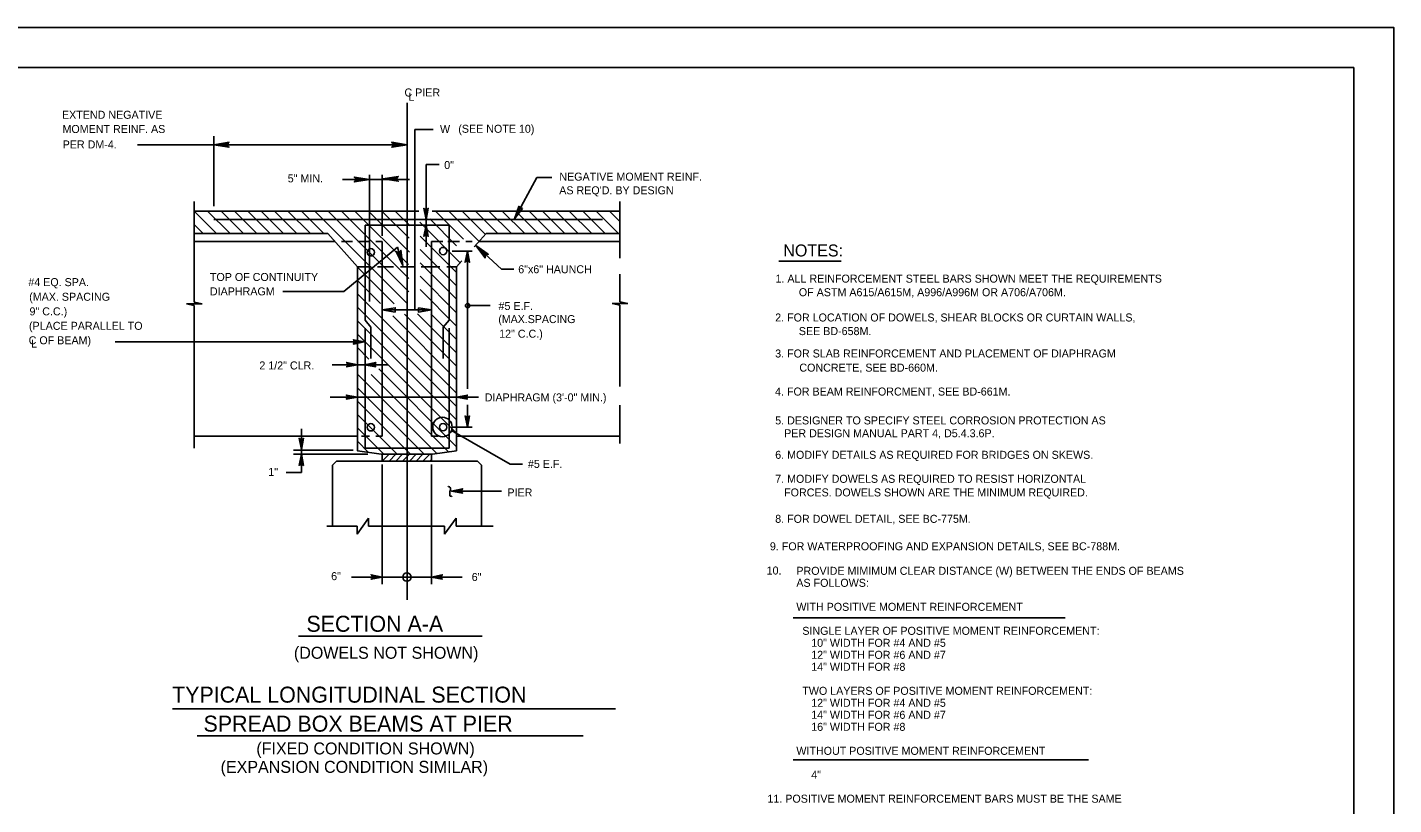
# Model space of a CAD drawing. Extents: x 641517 to 642372, y 298537 to 300319.
# Drawn here: x 641846 to 642358, y 300027 to 300319 of the extents above; entities that cross this region are included whole.
import ezdxf

# ---------------------------------------------------------------- set-up
doc = ezdxf.new("R2010")
doc.units = 0
for name, color, linetype in [('1', 7, 'Continuous'), ('2', 7, 'Continuous'), ('PLT-BNDY', 7, 'Continuous')]:
    doc.layers.add(name, color=color, linetype=linetype)

msp = doc.modelspace()

# ---------------------------------------------------------------- linework, layer by layer
at = {"layer": '2'}
for p, q in [((641557.05, 300303.62), (642343.05, 300303.62)), ((642343.05, 300303.62), (642343.05, 299739.62)), ((641988.08, 300290.27), (641988.08, 300103.92)), ((641915.63, 300251.52), (641915.63, 300277.77)), ((641991.07, 300212.72), (641991.07, 300280.32)), ((641997.88, 300280.32), (641991.07, 300280.32)), ((641988.08, 300274.62), (641886.98, 300274.62)), ((642000.17, 300267.18), (641995.32, 300267.18)), ((641995.32, 300246.57), (641995.32, 300267.18)), ((641989.03, 300261.57), (641963.93, 300261.57)), ((641973.98, 300215.82), (641973.98, 300263.32)), ((641978.78, 300240.42), (641978.78, 300263.32)), ((642028.37, 300246.79), (642036.78, 300262.28)), ((642042.39, 300262.28), (642036.78, 300262.28)), ((641908.28, 300215.52), (641908.28, 300253.32)), ((642067.88, 300253.32), (642067.88, 300232.08)), ((641908.28, 300249.35), (641908.66, 300249.72)), ((641908.28, 300249.72), (641908.28, 300249.72)), ((641908.28, 300249.72), (641916.68, 300241.32)), ((641908.28, 300249.72), (641992.56, 300249.72)), ((641913.31, 300249.72), (641921.71, 300241.32)), ((642061.4, 300246.57), (641915.63, 300246.57)), ((641918.33, 300249.72), (641926.73, 300241.32)), ((641923.35, 300249.72), (641931.75, 300241.32)), ((641928.38, 300249.72), (641936.78, 300241.32)), ((641933.4, 300249.72), (641941.8, 300241.32)), ((641938.42, 300249.72), (641946.82, 300241.32)), ((641943.45, 300249.72), (641951.85, 300241.32)), ((641948.47, 300249.72), (641956.87, 300241.32)), ((641953.49, 300249.72), (641988.23, 300214.99)), ((641958.52, 300249.72), (641988.82, 300219.42)), ((641963.54, 300249.72), (641988.8, 300224.47)), ((641968.56, 300249.72), (641988.66, 300229.63)), ((641973.59, 300249.72), (641989.02, 300234.29)), ((641978.61, 300249.72), (641988.83, 300239.51)), ((641983.63, 300249.72), (641989.2, 300244.16)), ((641995.32, 300244.46), (641995.32, 300246.57)), ((641996.58, 300246.83), (642006.67, 300236.73)), ((641997.47, 300249.72), (642067.88, 300249.72)), ((641998.7, 300249.72), (642009.28, 300239.14)), ((642003.73, 300249.72), (642015.12, 300238.33)), ((642008.75, 300249.72), (642017.49, 300240.99)), ((642013.77, 300249.72), (642022.17, 300241.32)), ((642018.8, 300249.72), (642027.2, 300241.32)), ((642023.82, 300249.72), (642032.22, 300241.32)), ((642028.84, 300249.72), (642037.24, 300241.32)), ((642033.87, 300249.72), (642042.27, 300241.32)), ((642038.89, 300249.72), (642047.29, 300241.32)), ((642043.91, 300249.72), (642052.31, 300241.32)), ((642048.94, 300249.72), (642057.34, 300241.32)), ((642053.96, 300249.72), (642062.36, 300241.32)), ((642058.98, 300249.72), (642067.38, 300241.32)), ((642064.01, 300249.72), (642067.88, 300245.85)), ((641908.28, 300244.7), (641911.66, 300241.32)), ((641908.28, 300241.32), (641958.38, 300241.32)), ((641969.48, 300228.87), (641958.38, 300241.32)), ((641972.33, 300244.43), (642003.83, 300244.43)), ((641972.33, 300244.43), (641972.33, 300208.77)), ((641992.83, 300245.55), (642008.02, 300230.37)), ((641995.32, 300236.25), (641995.32, 300244.43)), ((642003.83, 300244.43), (642003.83, 300208.77)), ((642017.78, 300241.32), (642013.3, 300236.29)), ((642017.78, 300241.32), (642067.88, 300241.32)), ((641961.08, 300238.32), (641908.28, 300238.32)), ((641967.69, 300238.32), (641963.48, 300238.32)), ((641984.46, 300236.21), (641964.38, 300219.53)), ((641969.66, 300238.32), (641974.05, 300238.32)), ((641976.38, 300238.32), (641978.78, 300238.32)), ((641978.78, 300165.27), (641978.78, 300238.32)), ((641986.54, 300229.34), (641984.46, 300236.21)), ((641993, 300240.36), (642006.68, 300226.67)), ((641997.23, 300165.27), (641997.23, 300238.32)), ((642001.45, 300238.32), (641997.23, 300238.32)), ((642003.42, 300238.32), (642007.81, 300238.32)), ((642010.14, 300238.32), (642012.54, 300238.32)), ((642013.88, 300236.82), (642023.48, 300227.97)), ((642015.08, 300238.32), (642067.88, 300238.32)), ((641993, 300235.34), (642006.68, 300221.65)), ((642012.49, 300234.7), (642005.03, 300234.7)), ((642008.62, 300231.04), (642006.68, 300228.87)), ((642010.77, 300183.08), (642010.77, 300234.7)), ((642127.54, 300230.95), (642150.82, 300230.95)), ((641969.48, 300159.87), (641969.48, 300228.87)), ((641969.48, 300228.87), (641974.58, 300228.87)), ((641969.48, 300228.71), (641983.29, 300214.9)), ((641976.98, 300228.87), (641982.98, 300228.87)), ((641985.68, 300228.87), (641990.63, 300228.87)), ((641993, 300230.31), (642006.68, 300216.63)), ((641993, 300225.29), (642006.68, 300211.6)), ((641993.33, 300228.87), (642000.35, 300228.87)), ((642003.05, 300228.87), (642006.68, 300228.87)), ((642006.68, 300228.87), (642006.68, 300159.87)), ((642028.13, 300227.97), (642023.48, 300227.97)), ((642067.88, 300215.67), (642067.88, 300226.02)), ((641969.48, 300223.69), (641978.08, 300215.1)), ((641993, 300220.27), (642006.68, 300206.58)), ((641908.28, 300215.52), (641911.28, 300214.92)), ((641964.38, 300219.53), (641941.47, 300219.53)), ((641969.48, 300218.66), (642006.68, 300181.46)), ((642065.03, 300215.07), (642070.88, 300215.07)), ((642065.03, 300215.07), (642067.88, 300214.47)), ((642067.88, 300215.67), (642070.88, 300215.07)), ((641905.43, 300214.92), (641911.28, 300214.92)), ((641905.43, 300214.92), (641908.28, 300214.32)), ((641908.28, 300160.77), (641908.28, 300214.32)), ((641969.48, 300213.64), (642006.68, 300176.44)), ((641997.23, 300212.65), (641978.78, 300212.65)), ((641982.7, 300210.47), (642006.68, 300186.49)), ((641987.13, 300211.07), (642006.68, 300191.51)), ((641992.06, 300211.15), (642006.68, 300196.53)), ((641997, 300211.24), (642006.68, 300201.56)), ((642010.77, 300214.29), (642019.25, 300214.29)), ((642067.88, 300184), (642067.88, 300214.47)), ((641969.48, 300208.62), (642006.68, 300171.42)), ((641974.54, 300206.2), (641972.33, 300208.77)), ((641972.33, 300205.77), (641972.33, 300160.77)), ((641974.54, 300206.2), (641974.54, 300194.43)), ((642001.64, 300206.21), (642003.83, 300208.77)), ((642001.64, 300206.21), (642001.64, 300194.43)), ((642003.83, 300205.77), (642003.83, 300160.77)), ((641972.03, 300200.73), (641878.68, 300200.73)), ((641969.48, 300203.59), (642006.68, 300166.39)), ((641969.48, 300198.57), (641973.81, 300194.24)), ((641981.03, 300192.07), (641960.03, 300192.07)), ((641977.49, 300190.56), (642006.68, 300161.37)), ((641969.48, 300188.52), (641999.25, 300158.76)), ((641974.61, 300188.42), (642003.62, 300159.41)), ((641969.48, 300179.97), (641959.28, 300179.97)), ((641969.48, 300183.5), (641994.46, 300158.52)), ((642006.68, 300179.97), (641969.48, 300179.97)), ((642014.93, 300179.97), (642006.68, 300179.97)), ((641969.48, 300178.48), (641989.44, 300158.52)), ((642010.77, 300168.68), (642010.77, 300177.05)), ((642067.88, 300162.57), (642067.88, 300176.97)), ((641969.48, 300173.45), (641984.41, 300158.52)), ((641908.28, 300165.27), (641969.63, 300165.27)), ((641948.48, 300158.52), (641948.48, 300168.12)), ((641969.48, 300168.43), (641979.39, 300158.52)), ((641970.99, 300165.27), (641974.05, 300165.27)), ((641976.38, 300165.27), (641978.78, 300165.27)), ((641997.23, 300165.27), (641999.8, 300165.27)), ((642004.75, 300167.43), (642026.74, 300154.82)), ((642012.49, 300168.68), (642005.03, 300168.68)), ((642006.53, 300165.27), (642067.88, 300165.27)), ((641967.83, 300160.02), (641945.48, 300160.02)), ((641969.48, 300163.41), (641973.65, 300159.24)), ((641969.48, 300160.03), (641969.67, 300159.84)), ((641969.48, 300159.87), (641978.33, 300158.52)), ((641972.33, 300160.77), (642003.83, 300160.77)), ((641997.68, 300158.52), (642006.68, 300159.87)), ((641973.38, 300158.52), (641945.48, 300158.52)), ((641948.48, 300151.63), (641948.48, 300158.52)), ((641960.18, 300154.47), (641961.68, 300155.97)), ((641960.18, 300154.47), (641960.18, 300131.52)), ((641961.68, 300155.97), (642014.48, 300155.97)), ((641997.68, 300158.52), (641978.33, 300158.52)), ((641978.78, 300155.97), (641978.78, 300158.52)), ((641978.78, 300158.52), (641978.78, 300158.52)), ((641978.78, 300158.52), (641978.78, 300158.52)), ((641978.78, 300158.52), (641978.78, 300158.52)), ((641978.78, 300155.98), (641981.33, 300158.52)), ((641978.78, 300154.73), (641978.78, 300109.77)), ((641981.33, 300155.97), (641983.88, 300158.52)), ((641983.87, 300155.97), (641986.42, 300158.52)), ((641986.42, 300155.97), (641988.97, 300158.52)), ((641988.96, 300155.97), (641991.51, 300158.52)), ((641991.51, 300155.97), (641994.06, 300158.52)), ((641994.05, 300155.97), (641996.6, 300158.52)), ((641996.6, 300155.97), (641997.23, 300156.61)), ((641997.23, 300155.97), (641997.23, 300158.52)), ((641997.23, 300154.73), (641997.23, 300109.77)), ((642015.98, 300154.47), (642014.48, 300155.97)), ((642015.98, 300154.47), (642015.98, 300131.52)), ((642031.39, 300154.82), (642026.74, 300154.82)), ((641942.77, 300151.63), (641948.48, 300151.63)), ((642023.48, 300144.72), (642004.73, 300144.72)), ((641969.33, 300128.52), (641973.68, 300134.52)), ((641973.68, 300134.52), (641973.68, 300131.52)), ((642002.18, 300128.52), (642006.53, 300134.52)), ((642006.53, 300134.52), (642006.53, 300131.52)), ((641969.33, 300131.52), (641957.99, 300131.52)), ((641969.33, 300131.52), (641969.33, 300128.52)), ((642002.18, 300131.52), (641973.68, 300131.52)), ((642002.18, 300131.52), (642002.18, 300128.52)), ((642020.33, 300131.52), (642006.53, 300131.52)), ((641988.08, 300120.42), (641988.08, 300120.42)), ((642008.78, 300112.47), (641967.23, 300112.47)), ((642132.93, 300097.2), (642234.86, 300097.2)), ((641947.39, 300090.34), (642016.24, 300090.34)), ((641900.12, 300063.01), (642066.25, 300063.01)), ((641909.41, 300052.89), (642054.09, 300052.89)), ((642132.93, 300043.92), (642243.59, 300043.92))]:
    msp.add_line(p, q, dxfattribs=at)
for points in [[(641921.03, 300273.87), (641920.88, 300274.32), (641915.63, 300274.62), (641921.03, 300273.87), (641921.33, 300273.72), (641915.63, 300274.62), (641920.88, 300274.77), (641921.03, 300275.22), (641915.63, 300274.62), (641921.33, 300275.52), (641921.03, 300275.22)], [(641982.68, 300275.22), (641982.83, 300274.92), (641988.08, 300274.62), (641982.68, 300275.22), (641982.38, 300275.52), (641988.08, 300274.62), (641982.83, 300274.32), (641982.68, 300273.87), (641988.08, 300274.62), (641982.38, 300273.72), (641982.68, 300273.87)], [(641968.58, 300262.32), (641968.73, 300261.87), (641973.98, 300261.57), (641968.58, 300262.32), (641968.28, 300262.47), (641973.98, 300261.57), (641968.73, 300261.27), (641968.58, 300260.97), (641973.98, 300261.57), (641968.28, 300260.67), (641968.58, 300260.97)], [(641984.49, 300261.22), (641984.34, 300261.52), (641979.09, 300261.82), (641984.49, 300261.22), (641984.79, 300260.92), (641979.09, 300261.82), (641984.34, 300262.12), (641984.49, 300262.42), (641979.09, 300261.82), (641984.79, 300262.72), (641984.49, 300262.42)], [(641995.92, 300250.47), (641995.47, 300250.47), (641995.32, 300246.57), (641995.92, 300250.47), (641996.07, 300250.77), (641995.32, 300246.57), (641995.02, 300250.47), (641994.72, 300250.47), (641995.32, 300246.57), (641994.42, 300250.77), (641994.72, 300250.47)], [(641994.72, 300240.53), (641995.02, 300240.68), (641995.32, 300244.43), (641994.72, 300240.53), (641994.42, 300240.23), (641995.32, 300244.43), (641995.47, 300240.68), (641995.92, 300240.53), (641995.32, 300244.43), (641996.07, 300240.23), (641995.92, 300240.53)], [(642017.33, 300232.62), (642017.48, 300232.92), (642013.88, 300236.82), (642017.33, 300232.62), (642017.33, 300232.17), (642013.88, 300236.82), (642017.78, 300233.37), (642018.23, 300233.52), (642013.88, 300236.82), (642018.53, 300233.52), (642018.23, 300233.52)], [(641985.74, 300234.73), (641985.35, 300234.46), (641986.54, 300229.34), (641985.74, 300234.73), (641985.8, 300235.06), (641986.54, 300229.34), (641984.77, 300234.29), (641984.44, 300234.35), (641986.54, 300229.34), (641984.07, 300234.56), (641984.44, 300234.35)], [(642010.17, 300230.8), (642010.47, 300230.95), (642010.77, 300234.7), (642010.17, 300230.8), (642009.87, 300230.5), (642010.77, 300234.7), (642010.92, 300230.95), (642011.37, 300230.8), (642010.77, 300234.7), (642011.52, 300230.5), (642011.37, 300230.8)], [(641968.13, 300201.33), (641968.28, 300200.88), (641972.03, 300200.73), (641968.13, 300201.33), (641967.98, 300201.48), (641972.03, 300200.73), (641968.28, 300200.43), (641968.13, 300200.13), (641972.03, 300200.73), (641967.98, 300199.83), (641968.13, 300200.13)], [(641965.58, 300192.67), (641965.73, 300192.37), (641969.48, 300192.07), (641965.58, 300192.67), (641965.43, 300192.97), (641969.48, 300192.07), (641965.73, 300191.92), (641965.58, 300191.47), (641969.48, 300192.07), (641965.43, 300191.32), (641965.58, 300191.47)], [(641976.23, 300191.47), (641976.08, 300191.92), (641972.18, 300192.07), (641976.23, 300191.47), (641976.38, 300191.32), (641972.18, 300192.07), (641976.08, 300192.37), (641976.23, 300192.67), (641972.18, 300192.07), (641976.38, 300192.97), (641976.23, 300192.67)], [(641965.43, 300180.57), (641965.58, 300180.27), (641969.48, 300179.97), (641965.43, 300180.57), (641965.28, 300180.72), (641969.48, 300179.97), (641965.58, 300179.67), (641965.43, 300179.37), (641969.48, 300179.97), (641965.28, 300179.22), (641965.43, 300179.37)], [(642010.58, 300179.37), (642010.43, 300179.67), (642006.68, 300179.97), (642010.58, 300179.37), (642010.73, 300179.22), (642006.68, 300179.97), (642010.43, 300180.12), (642010.58, 300180.57), (642006.68, 300179.97), (642010.73, 300180.72), (642010.58, 300180.57)], [(642011.37, 300172.58), (642010.92, 300172.58), (642010.77, 300168.68), (642011.37, 300172.58), (642011.52, 300172.88), (642010.77, 300168.68), (642010.47, 300172.58), (642010.17, 300172.58), (642010.77, 300168.68), (642009.87, 300172.88), (642010.17, 300172.58)], [(641949.08, 300164.37), (641948.63, 300164.22), (641948.48, 300160.32), (641949.08, 300164.37), (641949.23, 300164.52), (641948.48, 300160.32), (641948.18, 300164.22), (641947.88, 300164.37), (641948.48, 300160.32), (641947.58, 300164.52), (641947.88, 300164.37)], [(641947.88, 300154.62), (641948.18, 300154.62), (641948.48, 300158.52), (641947.88, 300154.62), (641947.58, 300154.32), (641948.48, 300158.52), (641948.63, 300154.77), (641948.93, 300154.62), (641948.48, 300158.52), (641949.23, 300154.32), (641948.93, 300154.62)], [(642008.78, 300144.12), (642008.63, 300144.57), (642004.73, 300144.72), (642008.78, 300144.12), (642008.93, 300143.97), (642004.73, 300144.72), (642008.63, 300145.02), (642008.78, 300145.32), (642004.73, 300144.72), (642008.93, 300145.62), (642008.78, 300145.32)], [(641974.88, 300113.07), (641975.03, 300112.77), (641978.78, 300112.47), (641974.88, 300113.07), (641974.58, 300113.37), (641978.78, 300112.47), (641975.03, 300112.32), (641974.88, 300111.87), (641978.78, 300112.47), (641974.58, 300111.72), (641974.88, 300111.87)], [(642001.13, 300111.87), (642000.98, 300112.32), (641997.23, 300112.47), (642001.13, 300111.87), (642001.28, 300111.72), (641997.23, 300112.47), (642000.98, 300112.77), (642001.13, 300113.07), (641997.23, 300112.47), (642001.28, 300113.37), (642001.13, 300113.07)]]:
    msp.add_lwpolyline(points, dxfattribs=at)
for points in [[(642031.41, 300250.67), (642028.37, 300246.79), (642029.99, 300251.44)], [(641983.64, 300211.84), (641978.78, 300212.65), (641983.64, 300213.45)], [(641992.37, 300213.47), (641997.23, 300212.65), (641992.37, 300211.85)], [(641992.37, 300213.47), (641997.23, 300212.65), (641992.37, 300211.85)]]:
    msp.add_lwpolyline(points, close=True, dxfattribs=at)
for centre, radius in [((641974.53, 300234.26), 1.38), ((642001.6, 300234.74), 1.38), ((642010.77, 300214.29), 0.79), ((641974.53, 300168.64), 1.38), ((642001.36, 300168.75), 3.63), ((642001.6, 300168.68), 1.38), ((641988.05, 300112.49), 1.6)]:
    msp.add_circle(centre, radius, dxfattribs=at)
msp.add_spline([(642003.38, 300146.37), (642003.98, 300146.37), (642004.28, 300146.07), (642004.43, 300145.47), (642004.28, 300144.87), (642004.13, 300144.27), (642004.13, 300143.67), (642004.13, 300143.07), (642004.58, 300142.77), (642005.03, 300142.77)], degree=3, dxfattribs=at)
at = {"layer": 'PLT-BNDY'}
msp.add_lwpolyline([(641517.05, 300318.62), (642358.05, 300318.62), (642358.05, 299724.62), (641517.05, 299724.62)], close=True, dxfattribs=at)

# ---------------------------------------------------------------- texts
at = {"layer": '1'}
for s, height, p in [('PROVIDE MIMIMUM CLEAR DISTANCE (W) BETWEEN THE ENDS OF BEAMS', 2.9999, (642134.07, 300113.32)), ('AS FOLLOWS:', 2.9999, (642134.07, 300108.82)), ('WITH POSITIVE MOMENT REINFORCEMENT', 2.9999, (642134.07, 300099.82)), ('  SINGLE LAYER OF POSITIVE MOMENT REINFORCEMENT:', 2.9999, (642134.07, 300090.82)), ('     10" WIDTH FOR #4 AND #5', 2.9999, (642134.07, 300086.32)), ('     12" WIDTH FOR #6 AND #7', 2.9999, (642134.07, 300081.82)), ('     14" WIDTH FOR #8', 2.9999, (642134.07, 300077.32)), ('  TWO LAYERS OF POSITIVE MOMENT REINFORCEMENT:', 2.9999, (642134.07, 300068.32)), ('     12" WIDTH FOR #4 AND #5', 2.9999, (642134.07, 300063.82)), ('     14" WIDTH FOR #6 AND #7', 2.9999, (642134.07, 300059.32)), ('     16" WIDTH FOR #8', 2.9999, (642134.07, 300054.82)), ('WITHOUT POSITIVE MOMENT REINFORCEMENT', 2.9999, (642134.07, 300045.82)), ('     4"', 3, (642134.07, 300036.82))]:
    msp.add_text(s, height=height, dxfattribs=at).set_placement(p)
at = {"layer": '2'}
for s, height, p in [('C PIER', 3, (641987.12, 300292.69)), ('L', 3, (641988.58, 300291.07)), ('EXTEND NEGATIVE', 2.9999, (641858.7, 300284.33)), ('MOMENT REINF. AS', 2.9999, (641858.89, 300279)), ('W', 3, (642000.45, 300278.99)), ('(SEE NOTE 10)', 2.9999, (642007.31, 300279.08)), ('PER DM-4.', 3, (641858.96, 300273.21)), ('0"', 3, (642002.03, 300265.48)), ('5" MIN.', 3, (641943.35, 300260.48)), ('NEGATIVE MOMENT REINF.', 2.9999, (642045.2, 300261.13)), ("AS REQ'D. BY DESIGN", 2.9999, (642045.16, 300256.01)), ('NOTES:', 4.5, (642129.17, 300232.7)), ('TOP OF CONTINUITY', 2.9999, (641914.17, 300223.51)), ('6"x6" HAUNCH', 2.9999, (642029.78, 300226.4)), ('1. ALL REINFORCEMENT STEEL BARS SHOWN MEET THE REQUIREMENTS', 3, (642126.25, 300222.89)), ('#4 EQ. SPA.', 2.9999, (641846.08, 300221.57)), ('DIAPHRAGM', 3, (641914.17, 300218.11)), ('OF ASTM A615/A615M, A996/A996M OR A706/A706M.', 3, (642135, 300217.79)), ('(MAX. SPACING', 2.9999, (641846.4, 300216.09)), ('#5 E.F.', 3, (642022.39, 300212.62)), ('9" C.C.)', 3, (641846.53, 300210.61)), ('(MAX.SPACING', 2.9699, (642022.32, 300207.72)), ('2. FOR LOCATION OF DOWELS, SHEAR BLOCKS OR CURTAIN WALLS,', 3, (642126.14, 300208.32)), ('(PLACE PARALLEL TO', 2.9999, (641846.34, 300205.19)), ('12" C.C.)', 3, (642022.63, 300202.23)), ('SEE BD-658M.', 3, (642135, 300203.21)), ('C OF BEAM)', 3, (641846.21, 300199.77)), ('L', 3, (641847.09, 300198.52)), ('3. FOR SLAB REINFORCEMENT AND PLACEMENT OF DIAPHRAGM', 3, (642126.14, 300194.82)), ('2 1/2" CLR.', 2.9999, (641932.71, 300190.33)), ('CONCRETE, SEE BD-660M.', 3, (642135.2, 300189.51)), ('DIAPHRAGM (3\'-0" MIN.) ', 2.9999, (642017.22, 300178.36)), ('4. FOR BEAM REINFORCMENT, SEE BD-661M.', 3, (642126.09, 300180.55)), ('5. DESIGNER TO SPECIFY STEEL CORROSION PROTECTION AS', 3, (642126.14, 300169.72)), ('   PER DESIGN MANUAL PART 4, D5.4.3.6P.', 3, (642126.14, 300164.91)), ('6. MODIFY DETAILS AS REQUIRED FOR BRIDGES ON SKEWS.', 3, (642126.14, 300156.82)), ('#5 E.F.', 3, (642033.41, 300153.41)), ('1"', 3, (641936.07, 300150.43)), ('7. MODIFY DOWELS AS REQUIRED TO RESIST HORIZONTAL', 3, (642126.14, 300147.82)), ('PIER', 3, (642025.72, 300142.71)), ('   FORCES. DOWELS SHOWN ARE THE MINIMUM REQUIRED.', 3, (642126.14, 300142.72)), ('8. FOR DOWEL DETAIL, SEE BC-775M.', 3, (642126.14, 300132.82)), (' 9. FOR WATERPROOFING AND EXPANSION DETAILS, SEE BC-788M.', 3, (642123.03, 300122.52)), ('6"', 3, (641959.63, 300111.32)), ('6"', 3, (642012.34, 300111)), ('10.', 3, (642122.92, 300113.43)), ('SECTION A-A', 6, (641950.37, 300091.96)), ('(DOWELS NOT SHOWN)', 4.5, (641945.66, 300081.84)), ('TYPICAL LONGITUDINAL SECTION', 6, (641900, 300065.39)), ('SPREAD BOX BEAMS AT PIER', 6, (641911.77, 300054.51)), ('(FIXED CONDITION SHOWN)', 4.5, (641931.58, 300045.96)), ('(EXPANSION CONDITION SIMILAR)', 4.5, (641918.18, 300039.06)), ('11. POSITIVE MOMENT REINFORCEMENT BARS MUST BE THE SAME', 3, (642123.23, 300027.88))]:
    msp.add_text(s, height=height, dxfattribs=at).set_placement(p)

doc.saveas('drawing.dxf')
